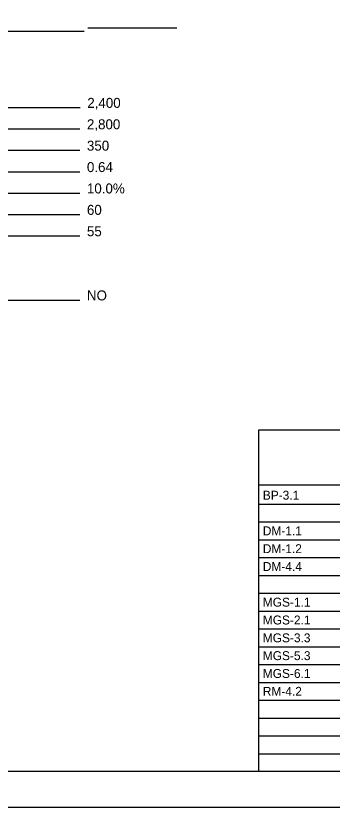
# Model space of a CAD drawing. Extents: x 0 to 48.6, y 0 to 22.
# Drawn here: x 6.74 to 11.18, y 0 to 11.1 of the extents above; entities that cross this region are included whole.
import ezdxf

# ---------------------------------------------------------------- set-up
doc = ezdxf.new("R2010")
doc.units = 0
for name, color, linetype in [('Default', 7, 'Continuous'), ('SH_Border', 7, 'Continuous'), ('SH_Cut_Line', 7, 'Continuous'), ('SH_Data', 7, 'Continuous'), ('SH_Text', 7, 'Continuous')]:
    doc.layers.add(name, color=color, linetype=linetype)

msp = doc.modelspace()

# ---------------------------------------------------------------- linework, layer by layer
at = {"layer": 'SH_Border'}
msp.add_lwpolyline([(1.5, 21.5), (33.5, 21.5), (33.5, 0.5), (1.5, 0.5)], close=True, dxfattribs=at)
at = {"layer": 'SH_Cut_Line'}
msp.add_lwpolyline([(0, 0), (34, 0), (34, 22), (0, 22)], close=True, dxfattribs=at)
at = {"layer": 'SH_Data'}
for p, q in [((7.7, 10.877), (3.347, 10.877)), ((9, 10.922), (7.75, 10.922)), ((7.642, 9.806), (3.871, 9.806)), ((7.637, 9.506), (4.189, 9.506)), ((7.637, 9.206), (4.872, 9.206)), ((7.637, 8.906), (4.604, 8.906)), ((7.637, 8.606), (4.189, 8.606)), ((7.637, 8.306), (3.346, 8.306)), ((7.637, 8.006), (3.242, 8.006)), ((7.637, 7.106), (3.267, 7.106)), ((10.15, 5.292), (23.6, 5.292)), ((10.15, 0.5), (10.15, 5.292)), ((10.15, 4.521), (23.6, 4.521)), ((10.15, 4.25), (21.875, 4.25)), ((10.15, 4), (21.875, 4)), ((10.15, 3.75), (21.875, 3.75)), ((10.15, 3.5), (23.6, 3.5)), ((10.15, 3.25), (23.6, 3.25)), ((10.15, 3), (23.6, 3)), ((10.15, 2.75), (23.6, 2.75)), ((10.15, 2.5), (23.6, 2.5)), ((10.15, 2.25), (23.6, 2.25)), ((10.15, 2), (23.6, 2)), ((10.15, 1.75), (23.6, 1.75)), ((10.15, 1.5), (23.6, 1.5)), ((10.15, 1.25), (23.6, 1.25)), ((10.15, 1), (23.6, 1)), ((10.15, 0.75), (23.6, 0.75))]:
    msp.add_line(p, q, dxfattribs=at)

# ---------------------------------------------------------------- texts
at = {"layer": 'Default'}
for s, p in [('BP-3.1', (10.205, 4.312)), ('DM-1.1', (10.205, 3.812)), ('DM-1.2', (10.205, 3.562)), ('DM-4.4', (10.205, 3.312)), ('MGS-1.1', (10.205, 2.812)), ('MGS-2.1', (10.205, 2.562)), ('MGS-3.3', (10.205, 2.312)), ('MGS-5.3', (10.205, 2.062)), ('MGS-6.1', (10.205, 1.812)), ('RM-4.2', (10.205, 1.562))]:
    msp.add_text(s, height=0.125, dxfattribs=at).set_placement(p)
at = {"layer": 'SH_Text'}
for s, p in [('2,400 ', (7.742, 9.806)), ('2,800 ', (7.737, 9.506)), ('350   ', (7.737, 9.206)), ('0.64  ', (7.737, 8.906)), ('10.0% ', (7.737, 8.606)), ('60    ', (7.737, 8.306)), ('55    ', (7.737, 8.006)), ('NO    ', (7.737, 7.106))]:
    msp.add_text(s, height=0.14, dxfattribs=at).set_placement(p)

doc.saveas('drawing.dxf')
